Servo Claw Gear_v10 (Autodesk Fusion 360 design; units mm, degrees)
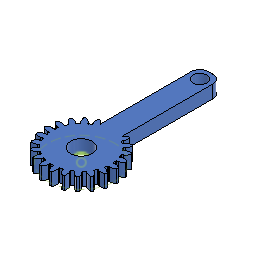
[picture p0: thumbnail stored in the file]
description: Spur Gear; Module: 0.7; Num Teeth: 22; Pressure Angle: 20.0; Backlash: 0.00 mm
sketch "Sketch1" plane through (0, 0, 0) normal (0, 0, 1) x axis (1, 0, 0)
  circle C1 centre (0, 0) radius 6.8092
  circle C2 centre (0, 0) radius 2.5
  dimension "d64" diameter C2 = 5
extrude "Extrude1" new body sketch "Sketch1" along normal blind 3
sketch "Sketch2" plane through (0, 0, 0) normal (0, 0, 1) x axis (1, 0, 0)
  curve K1 (8.3964, -0.2471) -> (7.2087, -0.6237)
  curve K2 (8.3964, 0.2471) -> (7.2087, 0.6237)
  line L1 (7.2087, -0.6237) -> (6.7739, -0.5869)
  line L2 (7.2087, 0.6237) -> (6.7739, 0.5869)
  line L3 (6.7739, 0.5869) -> (6.7739, -0.5869)
  arc A1 centre (0, 0) radius 8.4 clockwise from (8.3964, 0.2471) to (8.3964, -0.2471)
extrude "Extrude2" add sketch "Sketch2" along normal blind 3
fillet "Fillet1" radius 0.1
circular_pattern "C-Pattern1" countU 22 TotalAngle 360
sketch "Sketch3" plane through (0, 0, 0) normal (0, 0, 1) x axis (1, 0, 0)
  circle C1 centre (0, 0) radius 7.7
sketch "Sketch2" plane through (0, 0, 3) normal (0, 0, 1) x axis (-1, 0, 0)
  line L1 (-7.2087, 0.6237) -> (-6.8825, 0.5961)
  curve K1 (-8.3964, 0.2471) -> (-7.2087, 0.6237)
  curve K2 (-7.2087, -0.6237) -> (-8.3964, -0.2471)
  line L2 (-6.8825, -0.5961) -> (-7.2087, -0.6237)
  line L3 (-7.0924, -1.4325) -> (-6.7717, -1.3671)
  curve K3 (-8.1259, -2.1285) -> (-7.0924, -1.4325)
  curve K4 (-6.741, -2.6294) -> (-7.9866, -2.6026)
  line L4 (-6.4358, -2.511) -> (-6.741, -2.6294)
  line L5 (-6.4015, -3.3726) -> (-6.1122, -3.2195)
  curve K5 (-7.197, -4.3316) -> (-6.4015, -3.3726)
  curve K6 (-5.7272, -4.422) -> (-6.9299, -4.7473)
  line L6 (-5.4676, -4.2224) -> (-5.7272, -4.422)
  line L7 (-5.1921, -5.0395) -> (-4.9576, -4.8111)
  curve K7 (-5.6852, -6.1838) -> (-5.1921, -5.0395)
  curve K8 (-4.2493, -5.8564) -> (-5.3117, -6.5073)
  line L8 (-4.0566, -5.5918) -> (-4.2493, -5.8564)
  line L9 (-3.5619, -6.2982) -> (-3.4013, -6.0129)
  curve K9 (-3.7127, -7.535) -> (-3.5619, -6.2982)
  curve K10 (-2.4273, -6.8164) -> (-3.2632, -7.7402)
  line L10 (-2.3168, -6.5082) -> (-2.4273, -6.8164)
  line L11 (-1.6432, -7.0466) -> (-1.5695, -6.7276)
  curve K11 (-1.4395, -8.2757) -> (-1.6432, -7.0466)
  curve K12 (-0.4086, -7.2241) -> (-0.9504, -8.3461)
  line L12 (-0.3894, -6.8973) -> (-0.4086, -7.2241)
  line L13 (0.4086, -7.2241) -> (0.3894, -6.8973)
  curve K13 (0.9504, -8.3461) -> (0.4086, -7.2241)
  curve K14 (1.6432, -7.0466) -> (1.4395, -8.2757)
  line L14 (1.5695, -6.7276) -> (1.6432, -7.0466)
  line L15 (2.4273, -6.8164) -> (2.3168, -6.5082)
  curve K15 (3.2632, -7.7402) -> (2.4273, -6.8164)
  curve K16 (3.5619, -6.2982) -> (3.7127, -7.535)
  line L16 (3.4013, -6.0129) -> (3.5619, -6.2982)
  line L17 (4.2493, -5.8564) -> (4.0566, -5.5918)
  curve K17 (5.3117, -6.5073) -> (4.2493, -5.8564)
  curve K18 (5.1921, -5.0395) -> (5.6852, -6.1838)
  line L18 (4.9576, -4.8111) -> (5.1921, -5.0395)
  line L19 (5.7272, -4.422) -> (5.4676, -4.2224)
  curve K19 (6.9299, -4.7473) -> (5.7272, -4.422)
  curve K20 (6.4015, -3.3726) -> (7.197, -4.3316)
  line L20 (6.1122, -3.2195) -> (6.4015, -3.3726)
  line L21 (6.741, -2.6294) -> (6.4358, -2.511)
  curve K21 (7.9866, -2.6026) -> (6.741, -2.6294)
  curve K22 (7.0924, -1.4325) -> (8.1259, -2.1285)
  line L22 (6.7717, -1.3671) -> (7.0924, -1.4325)
  line L23 (7.2087, -0.6237) -> (6.8825, -0.5961)
  curve K23 (8.3964, -0.2471) -> (7.2087, -0.6237)
  curve K24 (7.2087, 0.6237) -> (8.3964, 0.2471)
  line L24 (6.8825, 0.5961) -> (7.2087, 0.6237)
  line L25 (7.0924, 1.4325) -> (6.7717, 1.3671)
  curve K25 (8.1259, 2.1285) -> (7.0924, 1.4325)
  curve K26 (6.741, 2.6294) -> (7.9866, 2.6026)
  line L26 (6.4358, 2.511) -> (6.741, 2.6294)
  line L27 (6.4015, 3.3726) -> (6.1122, 3.2195)
  curve K27 (7.197, 4.3316) -> (6.4015, 3.3726)
  curve K28 (5.7272, 4.422) -> (6.9299, 4.7473)
  line L28 (5.4676, 4.2224) -> (5.7272, 4.422)
  line L29 (5.1921, 5.0395) -> (4.9576, 4.8111)
  curve K29 (5.6852, 6.1838) -> (5.1921, 5.0395)
  curve K30 (4.2493, 5.8564) -> (5.3117, 6.5073)
  line L30 (4.0566, 5.5918) -> (4.2493, 5.8564)
  line L31 (3.5619, 6.2982) -> (3.4013, 6.0129)
  curve K31 (3.7127, 7.535) -> (3.5619, 6.2982)
  curve K32 (2.4273, 6.8164) -> (3.2632, 7.7402)
  line L32 (2.3168, 6.5082) -> (2.4273, 6.8164)
  line L33 (1.6432, 7.0466) -> (1.5695, 6.7276)
  curve K33 (1.4395, 8.2757) -> (1.6432, 7.0466)
  curve K34 (0.4086, 7.2241) -> (0.9504, 8.3461)
  line L34 (0.3894, 6.8973) -> (0.4086, 7.2241)
  line L35 (-0.4086, 7.2241) -> (-0.3894, 6.8973)
  curve K35 (-0.9504, 8.3461) -> (-0.4086, 7.2241)
  curve K36 (-1.6432, 7.0466) -> (-1.4395, 8.2757)
  line L36 (-1.5695, 6.7276) -> (-1.6432, 7.0466)
  line L37 (-2.4273, 6.8164) -> (-2.3168, 6.5082)
  curve K37 (-3.2632, 7.7402) -> (-2.4273, 6.8164)
  curve K38 (-3.5619, 6.2982) -> (-3.7127, 7.535)
  line L38 (-3.4013, 6.0129) -> (-3.5619, 6.2982)
  line L39 (-4.2493, 5.8564) -> (-4.0566, 5.5918)
  curve K39 (-5.3117, 6.5073) -> (-4.2493, 5.8564)
  curve K40 (-5.1921, 5.0395) -> (-5.6852, 6.1838)
  line L40 (-4.9576, 4.8111) -> (-5.1921, 5.0395)
  line L41 (-5.7272, 4.422) -> (-5.4676, 4.2224)
  curve K41 (-6.9299, 4.7473) -> (-5.7272, 4.422)
  curve K42 (-6.4015, 3.3726) -> (-7.197, 4.3316)
  line L42 (-6.1122, 3.2195) -> (-6.4015, 3.3726)
  line L43 (-6.741, 2.6294) -> (-6.4358, 2.511)
  curve K43 (-7.9866, 2.6026) -> (-6.741, 2.6294)
  curve K44 (-7.0924, 1.4325) -> (-8.1259, 2.1285)
  line L44 (-6.7717, 1.3671) -> (-7.0924, 1.4325)
  line L45 (2.5, 0) -> (0, 0)
  line L46 (-2.5, 0) -> (2.5, 0)
  line L47 (-2.5, -30) -> (-2.5, 0)
  line L48 (2.5, -30) -> (-2.5, -30)
  line L49 (2.5, 0) -> (2.5, -30)
  arc A1 centre (0, 0) radius 6.8092 clockwise from (-6.7746, 0.6857) to (-6.6934, 1.2507)
  arc A2 centre (-6.8741, 0.6958) radius 0.1 clockwise from (-6.7746, 0.6857) to (-6.8825, 0.5961)
  arc A3 centre (0, 0) radius 8.4 clockwise from (-8.3964, -0.2471) to (-8.3964, 0.2471)
  arc A4 centre (-6.8741, -0.6958) radius 0.1 clockwise from (-6.8825, -0.5961) to (-6.7746, -0.6857)
  arc A5 centre (0, 0) radius 6.8092 clockwise from (-6.6934, -1.2507) to (-6.7746, -0.6857)
  arc A6 centre (-6.7916, -1.2691) radius 0.1 clockwise from (-6.6934, -1.2507) to (-6.7717, -1.3671)
  arc A7 centre (0, 0) radius 8.4 clockwise from (-7.9866, -2.6026) to (-8.1259, -2.1285)
  arc A8 centre (-6.3996, -2.6042) radius 0.1 clockwise from (-6.4358, -2.511) to (-6.307, -2.5665)
  arc A9 centre (0, 0) radius 6.8092 clockwise from (-6.0699, -3.0858) to (-6.307, -2.5665)
  arc A10 centre (-6.159, -3.1311) radius 0.1 clockwise from (-6.0699, -3.0858) to (-6.1122, -3.2195)
  arc A11 centre (0, 0) radius 8.4 clockwise from (-6.9299, -4.7473) to (-7.197, -4.3316)
  arc A12 centre (-5.4067, -4.3017) radius 0.1 clockwise from (-5.4676, -4.2224) to (-5.3284, -4.2395)
  arc A13 centre (0, 0) radius 6.8092 clockwise from (-4.9546, -4.6709) to (-5.3284, -4.2395)
  arc A14 centre (-5.0274, -4.7395) radius 0.1 clockwise from (-4.9546, -4.6709) to (-4.9576, -4.8111)
  arc A15 centre (0, 0) radius 8.4 clockwise from (-5.3117, -6.5073) to (-5.6852, -6.1838)
  arc A16 centre (-3.9757, -5.6507) radius 0.1 clockwise from (-4.0566, -5.5918) to (-3.9182, -5.5689)
  arc A17 centre (0, 0) radius 6.8092 clockwise from (-3.438, -5.8775) to (-3.9182, -5.5689)
  arc A18 centre (-3.4885, -5.9639) radius 0.1 clockwise from (-3.438, -5.8775) to (-3.4013, -6.0129)
  arc A19 centre (0, 0) radius 8.4 clockwise from (-3.2632, -7.7402) to (-3.7127, -7.535)
  arc A20 centre (-2.2227, -6.5419) radius 0.1 clockwise from (-2.3168, -6.5082) to (-2.1905, -6.4472)
  arc A21 centre (0, 0) radius 6.8092 clockwise from (-1.6428, -6.608) to (-2.1905, -6.4472)
  arc A22 centre (-1.667, -6.7051) radius 0.1 clockwise from (-1.6428, -6.608) to (-1.5695, -6.7276)
  arc A23 centre (0, 0) radius 8.4 clockwise from (-0.9504, -8.3461) to (-1.4395, -8.2757)
  arc A24 centre (-0.2896, -6.9031) radius 0.1 clockwise from (-0.3894, -6.8973) to (-0.2854, -6.8032)
  arc A25 centre (0, 0) radius 6.8092 clockwise from (0.2854, -6.8032) to (-0.2854, -6.8032)
  arc A26 centre (0.2896, -6.9031) radius 0.1 clockwise from (0.2854, -6.8032) to (0.3894, -6.8973)
  arc A27 centre (0, 0) radius 8.4 clockwise from (1.4395, -8.2757) to (0.9504, -8.3461)
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  point P1 (0, 0)
  point P223 (0, 0)
  point P224 (2.5, 0)
  point P226 (-2.5, 0)
  point P228 (2.5, -30)
  coincident P1 P223
  horizontal L45
  horizontal L46
  vertical L47
  horizontal L48
  vertical L49
  dimension "d49" distance P223 P224 = 2.5
  dimension "d52" diameter = 3.2
  dimension "d58" distance P224 P226 = 5
  dimension "d59" distance P224 P228 = 30
extrude "Extrude3" add sketch "Sketch2" against normal blind 3
extrude "Extrude4" add sketch "Sketch2" against normal blind 3
fillet "Fillet3" radius 2
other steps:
create_component "CreateComponent4"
